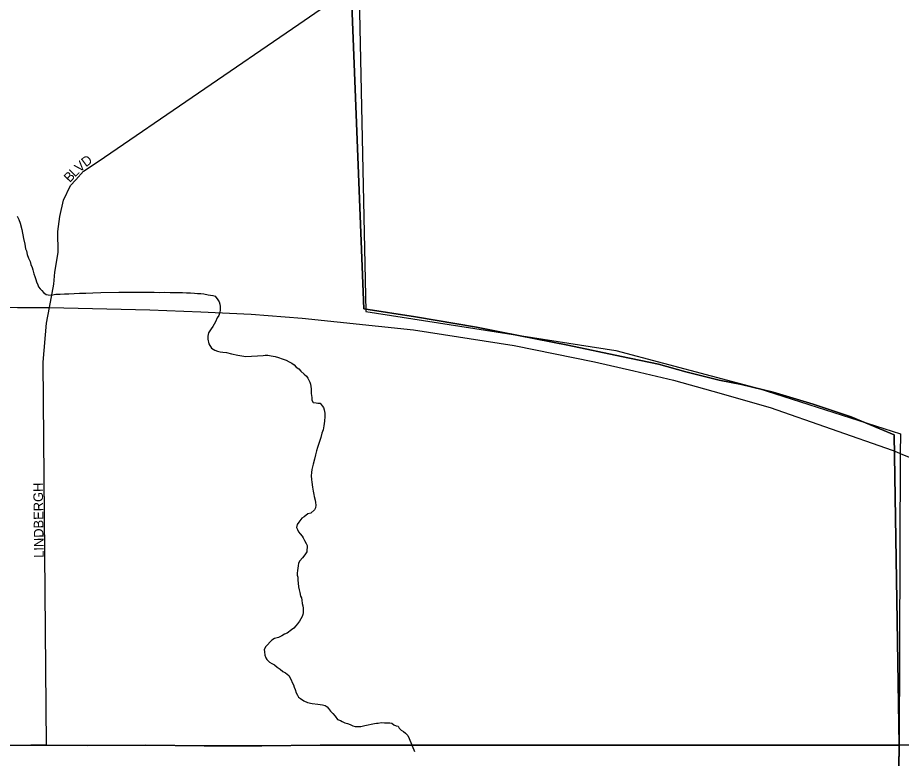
# Model space of a CAD drawing. Extents: x 2010165 to 2382125, y 1060529 to 1407316.
# Drawn here: x 2135077 to 2139658, y 1221171 to 1225012 of the extents above; entities that cross this region are included whole.
import ezdxf

# ---------------------------------------------------------------- set-up
doc = ezdxf.new("R2010")
doc.units = 0
for name, color, linetype in [('GM_X_Adjacent_County', 7, 'Continuous'), ('GM_X_City_Street', 7, 'Continuous'), ('GM_X_City_Street_Text', 7, 'Continuous'), ('GM_X_Corporation', 7, 'Continuous'), ('GM_X_County', 7, 'Continuous'), ('GM_X_Interstate_Route', 7, 'Continuous'), ('GM_X_Minor_River', 7, 'Continuous'), ('GM_X_Township', 7, 'Continuous')]:
    doc.layers.add(name, color=color, linetype=linetype)

msp = doc.modelspace()

# ---------------------------------------------------------------- linework, layer by layer
at = {"layer": 'GM_X_Adjacent_County'}
msp.add_lwpolyline([(2126567.4, 1221231.3), (2131919.6, 1221238.9), (2132570.2, 1221243.7), (2133969.3, 1221233.9), (2135145.8, 1221238.6), (2135226.5, 1221239.7), (2135440.8, 1221237.8), (2135741.4, 1221239.3), (2136043.5, 1221235.6), (2136342.6, 1221236.4), (2136645.5, 1221239.3), (2136937.2, 1221238.6), (2139646.1, 1221239.5), (2139604.7, 1218402.7)], dxfattribs=at)
at = {"layer": 'GM_X_City_Street'}
for points in [[(2135226.5, 1221239.7), (2135208.9, 1223225.9), (2135226.6, 1223426.9), (2135241.7, 1223508.5), (2135264.3, 1223630.4), (2135269, 1223692.7), (2135286.8, 1223793.4), (2135284.5, 1223903.7), (2135294.9, 1223980.2), (2135315.1, 1224064.9), (2135351.5, 1224141.9), (2135378.9, 1224170.6), (2135417.9, 1224215.6), (2135494.9, 1224265.5), (2136534.2, 1224978.8), (2138042.8, 1226017.5)], [(2132570.1, 1221243.7), (2133969.3, 1221233.9), (2135145.8, 1221238.6), (2135226.5, 1221239.7), (2135440.8, 1221237.8), (2135741.4, 1221239.3), (2136043.5, 1221235.6), (2136342.6, 1221236.4), (2136645.5, 1221239.3), (2136937.2, 1221238.6), (2139646.1, 1221239.5)], [(2139605, 1218426.1), (2139646.1, 1221239.5)], [(2139646.1, 1221239.5), (2140813.5, 1221242), (2142121.3, 1221250.2), (2142587.6, 1221252.6), (2142825.7, 1221254.1), (2143061.9, 1221255.7)]]:
    msp.add_lwpolyline(points, dxfattribs=at)
at = {"layer": 'GM_X_Corporation'}
for points in [[(2136805.8, 1225168.6), (2136871.2, 1223502.8), (2137139.4, 1223460.6), (2137455.6, 1223406.7), (2137575.8, 1223383.5), (2137761.9, 1223346.7), (2137928.1, 1223313.8), (2138206.4, 1223255.6), (2138398.6, 1223214.8), (2138540.8, 1223175.7), (2138713.1, 1223132.9), (2138829.2, 1223109.6), (2138993.4, 1223070.7), (2139199.7, 1223008), (2139398.1, 1222941.2), (2139620.6, 1222848.6), (2139646.1, 1221239.5), (2136937.2, 1221238.6), (2136645.5, 1221239.3), (2136342.6, 1221236.4), (2136043.5, 1221235.6), (2135741.4, 1221239.3), (2135440.8, 1221237.8), (2135226.5, 1221239.7), (2135145.8, 1221238.6), (2133969.3, 1221233.9)], [(2140813.5, 1221242), (2139646.1, 1221239.5), (2139620.6, 1222848.6), (2139398.1, 1222941.2), (2139199.7, 1223008), (2138993.4, 1223070.7), (2138829.2, 1223109.6), (2138713.1, 1223132.9), (2138540.8, 1223175.7), (2138398.6, 1223214.8), (2138206.4, 1223255.6), (2137928.1, 1223313.8), (2137761.9, 1223346.7), (2137575.8, 1223383.5), (2137455.6, 1223406.7), (2137139.4, 1223460.6), (2136871.2, 1223502.8), (2136805.8, 1225168.6)], [(2139563.1, 1207294.1), (2139646.1, 1221239.5), (2140813.5, 1221242), (2142121.3, 1221250.2), (2142587.6, 1221252.6), (2142825.7, 1221254.1), (2144579, 1220185.1)]]:
    msp.add_lwpolyline(points, dxfattribs=at)
at = {"layer": 'GM_X_County'}
msp.add_lwpolyline([(2139604.7, 1218402.7), (2139646.1, 1221239.5), (2136937.2, 1221238.6), (2136645.5, 1221239.3), (2136342.6, 1221236.4), (2136043.5, 1221235.6), (2135741.4, 1221239.3), (2135440.8, 1221237.8), (2135226.5, 1221239.7), (2135145.8, 1221238.6), (2133969.3, 1221233.9), (2132570.2, 1221243.7), (2131919.6, 1221238.9), (2126567.4, 1221231.3)], dxfattribs=at)
at = {"layer": 'GM_X_Interstate_Route'}
for points in [[(2132122, 1223568.4), (2132754.5, 1223556.1), (2133070.4, 1223547.3), (2133441.3, 1223538.9), (2133809.4, 1223534), (2134128.1, 1223528.8), (2134548.5, 1223520.7), (2134812.2, 1223515.2), (2135075.9, 1223509.7), (2135241.7, 1223508.5), (2135762.8, 1223496), (2136026.5, 1223486.9), (2136287.6, 1223474.1), (2136551.4, 1223454), (2137128.7, 1223392.3), (2137651.1, 1223312), (2138066.5, 1223227.3), (2138270.1, 1223181.3), (2138476.5, 1223131.7), (2138680.1, 1223074.8), (2138977.2, 1222989.7), (2139610, 1222769.1), (2139632.9, 1222759.9)], [(2139632.9, 1222759.9), (2139651.5, 1222752.4), (2140077, 1222581.4), (2140639.4, 1222327.4), (2141295.9, 1221976.7), (2142116.7, 1221519.6), (2142587.6, 1221252.6)]]:
    msp.add_lwpolyline(points, dxfattribs=at)
at = {"layer": 'GM_X_Minor_River'}
for points in [[(2135073.5, 1223981.8), (2135083.8, 1223965.9), (2135090.1, 1223945.9), (2135098.6, 1223913.9), (2135107.3, 1223865.9), (2135113.7, 1223837.9), (2135115.9, 1223825.9), (2135118.1, 1223813.9), (2135122.2, 1223801.9), (2135126.5, 1223783.9), (2135132.8, 1223763.9), (2135141.1, 1223748), (2135145.3, 1223732), (2135151.6, 1223716), (2135155.7, 1223704.1), (2135160, 1223684.1), (2135166.3, 1223670.1), (2135170.5, 1223654.1), (2135174.7, 1223642.1), (2135180.9, 1223626.2), (2135185.1, 1223616.2), (2135193.3, 1223606.3), (2135201.4, 1223596.3), (2135211.6, 1223586.5), (2135223.8, 1223576.6), (2135235.8, 1223574.8), (2135249.9, 1223573), (2135273.9, 1223577.3), (2135297.9, 1223577.7), (2135320, 1223580), (2135342, 1223580.3), (2135370.1, 1223580.8), (2135398.1, 1223583.2), (2135430.2, 1223583.6), (2135466.3, 1223584.2), (2135508.4, 1223586.8), (2135600.6, 1223588.1), (2135632.7, 1223588.6), (2135730.9, 1223588), (2135759, 1223588.4), (2135785.1, 1223588.8), (2135811.1, 1223587.2), (2135837.2, 1223587.6), (2135867.3, 1223586), (2135883.3, 1223586.2), (2135895.4, 1223586.4), (2135911.4, 1223586.6), (2135931.5, 1223586.9), (2135951.5, 1223585.2), (2135973.6, 1223585.5), (2135993.7, 1223583.8), (2136009.7, 1223582), (2136025.8, 1223582.3), (2136041.8, 1223580.5), (2136064, 1223574.8), (2136088.1, 1223571.1), (2136100.2, 1223567.3), (2136114.5, 1223549.5), (2136120.7, 1223537.5), (2136124.8, 1223525.5), (2136127, 1223513.5), (2136127.2, 1223503.5), (2136127.3, 1223493.4), (2136123.5, 1223479.3), (2136119.7, 1223467.3), (2136111.8, 1223455.1), (2136102.1, 1223434.9), (2136096.3, 1223422.8), (2136088.4, 1223410.6), (2136080.6, 1223398.4), (2136072.7, 1223388.3), (2136066.8, 1223378.2), (2136063.1, 1223360.1), (2136063.3, 1223344), (2136067.7, 1223320), (2136082, 1223298.1)], [(2136082, 1223298.1), (2136098.2, 1223288.3), (2136112.3, 1223282.5), (2136126.4, 1223278.7), (2136140.5, 1223276.9), (2136158.6, 1223275.2), (2136184.7, 1223269.5), (2136218.9, 1223262), (2136259.1, 1223254.6), (2136349.3, 1223259.9), (2136359.3, 1223262), (2136373.3, 1223262.2), (2136391.4, 1223258.5), (2136411.5, 1223254.8), (2136429.6, 1223249), (2136447.8, 1223243.3), (2136467.9, 1223235.5), (2136484.1, 1223227.7), (2136498.2, 1223219.9), (2136510.4, 1223212.1), (2136520.6, 1223200.2), (2136534.8, 1223190.3), (2136545, 1223178.4), (2136561.2, 1223162.6), (2136573.4, 1223152.8), (2136581.6, 1223142.9), (2136591.9, 1223120.9), (2136594.1, 1223110.9), (2136596.3, 1223098.9), (2136598.4, 1223086.9), (2136598.6, 1223076.9), (2136598.8, 1223062.8), (2136601.1, 1223042.8), (2136601.3, 1223028.8), (2136609.5, 1223016.8), (2136623.5, 1223015.1), (2136633.6, 1223013.2), (2136645.6, 1223013.4), (2136655.9, 1222999.5), (2136662, 1222989.5), (2136666.2, 1222977.5), (2136668.4, 1222961.5), (2136668.7, 1222943.5), (2136667, 1222919.4), (2136663.4, 1222895.2), (2136659.7, 1222875.1), (2136653.9, 1222857), (2136648.2, 1222834.8), (2136630.9, 1222782.4), (2136625.1, 1222766.2), (2136621.5, 1222744.1), (2136615.8, 1222722), (2136608.1, 1222695.8), (2136602.5, 1222669.6), (2136600.7, 1222653.5), (2136599, 1222635.4), (2136599.2, 1222617.4), (2136601.4, 1222603.3), (2136605.8, 1222577.3), (2136608.1, 1222557.3), (2136612.4, 1222539.3), (2136614.5, 1222529.3), (2136618.9, 1222509.3), (2136621, 1222497.3), (2136623.2, 1222483.3), (2136621.4, 1222469.2), (2136615.6, 1222459.1), (2136595.8, 1222442.7), (2136581.8, 1222438.5), (2136561.9, 1222424.2), (2136550, 1222416), (2136534.3, 1222395.7), (2136526.4, 1222383.5), (2136522.7, 1222367.4), (2136526.8, 1222357.4), (2136533, 1222345.5), (2136541.2, 1222335.6), (2136551.4, 1222323.7), (2136557.5, 1222313.7), (2136563.7, 1222299.8), (2136572, 1222285.8), (2136578.1, 1222273.9), (2136576.6, 1222241.8), (2136564.8, 1222225.6), (2136553, 1222211.3), (2136539.2, 1222195.1), (2136533.4, 1222182.9), (2136531.5, 1222168.9), (2136529.7, 1222156.8), (2136527.9, 1222144.7), (2136526.1, 1222130.7), (2136526.2, 1222120.6), (2136528.4, 1222110.6), (2136528.6, 1222094.6), (2136530.9, 1222078.6), (2136533.1, 1222060.5), (2136535.4, 1222044.5), (2136539.6, 1222030.5), (2136543.8, 1222012.5), (2136548, 1222002.6), (2136550.2, 1221990.6)], [(2136550.2, 1221990.6), (2136552.4, 1221974.5), (2136554.6, 1221962.5), (2136556.8, 1221950.5), (2136557, 1221938.5), (2136557.1, 1221926.4), (2136555.3, 1221916.4), (2136551.4, 1221906.3), (2136545.6, 1221894.2), (2136537.7, 1221882), (2136527.9, 1221867.8), (2136518, 1221857.6), (2136508.2, 1221845.4), (2136496.3, 1221837.2), (2136474.4, 1221820.9), (2136460.5, 1221814.6), (2136446.6, 1221806.4), (2136428.7, 1221798.1), (2136408.7, 1221791.8), (2136394.8, 1221783.6), (2136363.2, 1221751), (2136355.4, 1221734.9), (2136355.6, 1221722.8), (2136357.8, 1221706.8), (2136364, 1221692.8), (2136368.2, 1221682.9), (2136382.4, 1221669), (2136394.5, 1221663.2), (2136408.7, 1221655.4), (2136422.9, 1221643.5), (2136437.1, 1221633.7), (2136451.3, 1221621.9), (2136465.4, 1221614.1), (2136481.7, 1221600.2), (2136494, 1221578.3), (2136500.2, 1221564.4), (2136506.4, 1221552.4), (2136510.6, 1221540.5), (2136514.8, 1221528.5), (2136521, 1221510.5), (2136527.2, 1221498.6), (2136533.4, 1221488.6), (2136543.5, 1221480.7), (2136559.8, 1221468.9), (2136579.9, 1221461.2), (2136604.1, 1221455.5), (2136632.2, 1221451.9), (2136656.3, 1221448.3), (2136670.4, 1221444.4), (2136680.5, 1221438.6), (2136688.7, 1221428.7), (2136698.9, 1221414.8), (2136711.1, 1221402.9), (2136723.3, 1221389), (2136735.6, 1221373.2), (2136749.7, 1221367.3), (2136759.8, 1221361.5), (2136772, 1221355.6), (2136786, 1221351.8), (2136800.2, 1221346), (2136814.3, 1221340.2), (2136826.4, 1221336.4), (2136840.4, 1221336.6), (2136856.4, 1221336.8), (2136876.4, 1221341.1), (2136926.4, 1221351.9), (2136936.4, 1221354), (2136946.4, 1221354.2), (2136960.4, 1221356.4), (2136978.5, 1221354.6), (2137006.6, 1221355), (2137016.6, 1221353.2), (2137026.8, 1221345.3), (2137038.9, 1221339.5), (2137048.9, 1221337.6), (2137055.1, 1221327.6), (2137065.3, 1221317.8), (2137077.4, 1221309.9), (2137087.5, 1221302), (2137099.7, 1221290.2), (2137106, 1221274.2), (2137133.9, 1221206.5)]]:
    msp.add_lwpolyline(points, dxfattribs=at)
at = {"layer": 'GM_X_Township'}
msp.add_lwpolyline([(2136847, 1225123.7), (2136882.5, 1223487.8), (2138178, 1223285.3), (2138918.5, 1223089.4), (2139653.2, 1222853.3), (2139651.5, 1222752.4), (2139646.1, 1221239.5), (2136937.2, 1221238.6), (2136645.5, 1221239.3), (2136342.6, 1221236.4), (2136043.5, 1221235.6), (2135741.4, 1221239.3), (2135440.8, 1221237.8), (2135226.5, 1221239.7), (2135145.8, 1221238.6), (2133969.3, 1221233.9), (2132570.2, 1221243.7), (2131919.6, 1221238.9), (2126567.4, 1221231.3)], dxfattribs=at)

# ---------------------------------------------------------------- texts
at = {"layer": 'GM_X_City_Street_Text'}
for s, rotation, p in [('D', 37.4244, (2135430.7, 1224235.1)), ('V', 41.1933, (2135398.3, 1224206.7)), ('B', 46.8467, (2135347.2, 1224153.8)), ('L', 44.9622, (2135374, 1224182.4)), ('LINDBERGH', 90.7171, (2135212.5, 1222211.1))]:
    msp.add_text(s, height=50, rotation=rotation, dxfattribs=at).set_placement(p)

doc.saveas('drawing.dxf')
